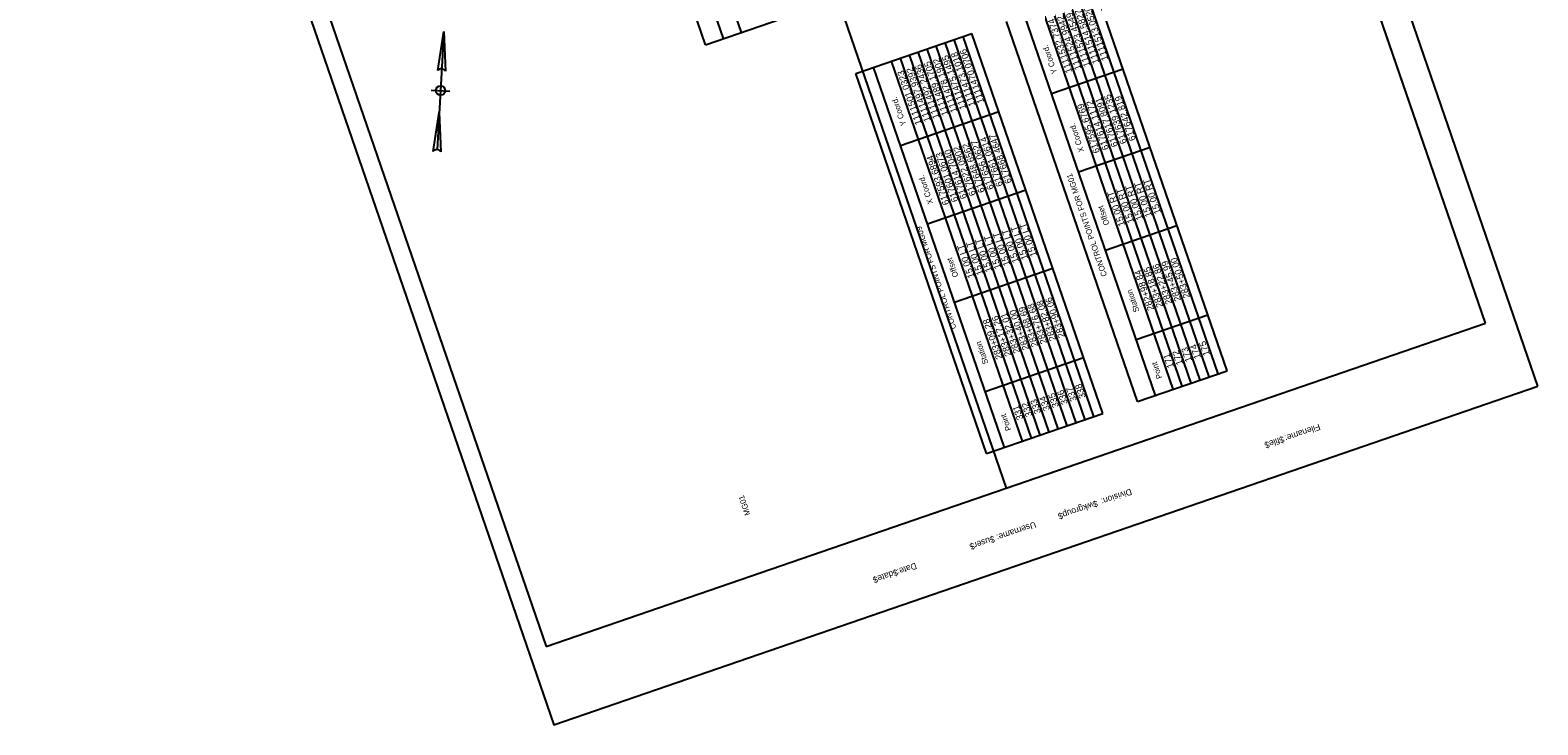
# Model space of a CAD drawing. Extents: x 1111039 to 1111836, y 617707 to 618808.
# Drawn here: x 1111039 to 1111836, y 617707 to 618074 of the extents above; entities that cross this region are included whole.
import ezdxf

# ---------------------------------------------------------------- set-up
doc = ezdxf.new("R2010")
doc.units = 0
for name, color, linetype in [('ANNOTATION', 7, 'Continuous'), ('BORDER', 7, 'Continuous'), ('CLIPS', 7, 'Continuous'), ('D_Roadway_Centerline_Text', 7, 'Continuous'), ('H_V CONTROLS', 7, 'Continuous'), ('PLOT BOUNDARY', 7, 'Continuous')]:
    doc.layers.add(name, color=color, linetype=linetype)

msp = doc.modelspace()

# ---------------------------------------------------------------- linework, layer by layer
at = {"layer": 'BORDER'}
for p, q in [((1111807.98, 617919.56), (1111547.52, 618675.97)), ((1111051.13, 618505.05), (1111311.58, 617748.63)), ((1111311.58, 617748.63), (1111807.98, 617919.56))]:
    msp.add_line(p, q, dxfattribs=at)
at = {"layer": 'CLIPS'}
msp.add_lwpolyline([(1111807.98, 617919.56), (1111563.8, 618628.7), (1111310.4, 618541.44), (1111554.58, 617832.3)], close=True, dxfattribs=at)
at = {"layer": 'H_V CONTROLS'}
for p, q in [((1111395.79, 618066.68), (1111326.61, 618267.61)), ((1111405.25, 618069.94), (1111336.06, 618270.86)), ((1111414.7, 618073.2), (1111345.52, 618274.12)), ((1111395.79, 618066.68), (1111584.9, 618131.8)), ((1111661.89, 617891.1), (1111592.71, 618092.02)), ((1111666.62, 617892.73), (1111597.44, 618093.65)), ((1111671.35, 617894.36), (1111602.17, 618095.28)), ((1111671.35, 617894.36), (1111602.17, 618095.28)), ((1111642.98, 617884.59), (1111573.8, 618085.51)), ((1111647.71, 617886.22), (1111578.53, 618087.14)), ((1111652.44, 617887.85), (1111583.26, 618088.77)), ((1111657.17, 617889.47), (1111587.98, 618090.4)), ((1111624.07, 617878.08), (1111554.89, 618079)), ((1111633.53, 617881.33), (1111564.35, 618082.26)), ((1111257.53, 618073.67), (1111253.89, 618011.28)), ((1111254.24, 618053), (1111257.53, 618073.67)), ((1111257.53, 618073.67), (1111258.4, 618052.75)), ((1111475.12, 618051.53), (1111536.57, 618072.69)), ((1111591.57, 617866.89), (1111522.39, 618067.81)), ((1111596.3, 617868.52), (1111527.12, 618069.44)), ((1111601.03, 617870.14), (1111531.85, 618071.07)), ((1111605.76, 617871.77), (1111536.57, 618072.69)), ((1111605.76, 617871.77), (1111536.57, 618072.69)), ((1111572.66, 617860.38), (1111503.48, 618061.3)), ((1111577.39, 617862), (1111508.21, 618062.93)), ((1111582.12, 617863.63), (1111512.94, 618064.55)), ((1111586.85, 617865.26), (1111517.66, 618066.18)), ((1111553.75, 617853.87), (1111484.57, 618054.79)), ((1111563.21, 617857.12), (1111494.03, 618058.04)), ((1111567.94, 617858.75), (1111498.75, 618059.67)), ((1111578.59, 618040.89), (1111616.41, 618053.91)), ((1111544.3, 617850.61), (1111475.12, 618051.53)), ((1111250.72, 618042.77), (1111260.7, 618042.18)), ((1111251.75, 618010.28), (1111255.04, 618030.96)), ((1111255.04, 618030.96), (1111255.91, 618010.04)), ((1111498.81, 618013.42), (1111550.82, 618031.33)), ((1111592.83, 617999.52), (1111630.65, 618012.55)), ((1111513.06, 617972.05), (1111565.06, 617989.96)), ((1111607.08, 617958.16), (1111644.9, 617971.18)), ((1111527.3, 617930.69), (1111579.3, 617948.59)), ((1111623.35, 617910.88), (1111661.17, 617923.9)), ((1111543.58, 617883.41), (1111595.58, 617901.32)), ((1111624.07, 617878.08), (1111671.35, 617894.36)), ((1111544.3, 617850.61), (1111605.76, 617871.77))]:
    msp.add_line(p, q, dxfattribs=at)
msp.add_circle((1111255.71, 618042.48), 2.5, dxfattribs=at)
for centre in [(1111256.24, 618051.5), (1111253.75, 618008.78)]:
    msp.add_arc(centre, 2.5, 30.21826, 143.10365, dxfattribs=at)
at = {"layer": 'PLOT BOUNDARY'}
msp.add_lwpolyline([(1111835.61, 617886.27), (1111558.88, 618689.96), (1111038.85, 618510.9), (1111315.58, 617707.21)], close=True, dxfattribs=at)

# ---------------------------------------------------------------- texts
at = {"layer": 'ANNOTATION'}
for s, height, p in [('1111514.5827', 3.5156, (1111603.9, 618057.31)), ('1111513.0520', 3.5156, (1111608.64, 618058.94)), ('1111532.7374', 3.5156, (1111589.65, 618052.41)), ('1111524.9942', 3.5156, (1111594.44, 618054.06)), ('1111523.4549', 3.5156, (1111599.2, 618055.7)), ('1111475.1495', 3.5156, (1111533.62, 618033.11)), ('1111473.1018', 3.5156, (1111538.41, 618034.76)), ('1111470.0706', 3.5156, (1111543.08, 618036.37)), ('1111501.0323', 3.5156, (1111510.09, 618025.01)), ('1111497.9392', 3.5156, (1111514.8, 618026.63)), ('1111492.2436', 3.5156, (1111519.42, 618028.23)), ('1111489.1705', 3.5156, (1111524.16, 618029.86)), ('1111478.1902', 3.5156, (1111528.93, 618031.5)), ('617614.1172', 3.5156, (1111609.03, 618011.67)), ('617617.8091', 3.5156, (1111613.8, 618013.31)), ('617639.1235', 3.5156, (1111618.49, 618014.92)), ('617642.819', 3.516, (1111623.23, 618016.55)), ('617595.6769', 3.5156, (1111604.24, 618010.02)), ('617622.0902', 3.5156, (1111538.76, 617987.47)), ('617648.6562', 3.5156, (1111543.52, 617989.11)), ('617656.0627', 3.5156, (1111548.22, 617990.72)), ('617661.0614', 3.5156, (1111553.01, 617992.37)), ('617668.4647', 3.5156, (1111557.68, 617993.98)), ('617593.6894', 3.5156, (1111524.68, 617982.62)), ('617601.0673', 3.5156, (1111529.4, 617984.24)), ('617614.7040', 3.5156, (1111534.02, 617985.84)), ('15.00 RT', 3.516, (1111617.55, 617971.39)), ('15.00 RT', 3.516, (1111622.34, 617973.04)), ('15.00 RT', 3.516, (1111627.1, 617974.68)), ('15.00 RT', 3.516, (1111631.79, 617976.29)), ('15.00 RT', 3.516, (1111636.53, 617977.92)), ('15.00 LT', 3.516, (1111552.06, 617948.84)), ('15.00 LT', 3.516, (1111556.83, 617950.48)), ('15.00 LT', 3.516, (1111561.52, 617952.09)), ('15.00 LT', 3.516, (1111566.31, 617953.74)), ('15.00 LT', 3.516, (1111570.98, 617955.35)), ('15.00 LT', 3.516, (1111537.98, 617943.99)), ('15.00 LT', 3.516, (1111542.7, 617945.61)), ('15.00 LT', 3.516, (1111547.32, 617947.21)), ('283+18.85', 3.516, (1111637.67, 617928.51)), ('283+22.86', 3.516, (1111642.43, 617930.15)), ('283+45.99', 3.516, (1111647.12, 617931.77)), ('283+50.00', 3.516, (1111651.87, 617933.4)), ('282+98.84', 3.516, (1111632.88, 617926.86)), ('283+90.06', 3.516, (1111585.75, 617912.43)), ('283+32.01', 3.516, (1111562.1, 617904.29)), ('283+40.00', 3.516, (1111566.84, 617905.92)), ('283+68.69', 3.516, (1111571.6, 617907.56)), ('283+76.68', 3.516, (1111576.3, 617909.18)), ('283+82.08', 3.516, (1111581.09, 617910.83)), ('283+09.28', 3.516, (1111552.76, 617901.07)), ('283+17.26', 3.516, (1111557.48, 617902.7)), ('175', 3.516, (1111662.33, 617903)), ('171', 3.516, (1111643.35, 617896.46)), ('172', 3.516, (1111648.13, 617898.11)), ('173', 3.516, (1111652.9, 617899.75)), ('174', 3.516, (1111657.59, 617901.37)), ('337', 3.516, (1111592.11, 617878.82)), ('338', 3.516, (1111596.78, 617880.43)), ('332', 3.516, (1111568.5, 617870.69)), ('333', 3.516, (1111573.12, 617872.28)), ('334', 3.516, (1111577.86, 617873.91)), ('335', 3.516, (1111582.63, 617875.55)), ('336', 3.516, (1111587.32, 617877.17)), ('331', 3.516, (1111563.78, 617869.06))]:
    msp.add_text(s, height=height, rotation=109, dxfattribs=at).set_placement(p)
at = {"layer": 'BORDER'}
for s, p in [('Filename:', (1111719.98, 617866.44)), ('$file$', (1111700.95, 617859.88)), ('Division:', (1111620.38, 617832.14)), ('$wkgroup$', (1111602.4, 617825.95)), ('Username:', (1111569.79, 617814.72)), ('$user$', (1111547.93, 617807.2)), ('$date$', (1111496.81, 617789.59)), ('Date:', (1111506.68, 617792.99))]:
    msp.add_text(s, height=3.348, rotation=199, dxfattribs=at).set_placement(p)
at = {"layer": 'D_Roadway_Centerline_Text'}
msp.add_text('MG01', height=3, rotation=108.7899, dxfattribs=at).set_placement((1111419.49, 617818.5))
at = {"layer": 'H_V CONTROLS'}
for s, p in [('Y Coord.', (1111581.67, 618051.91)), ('Y Coord.', (1111501.9, 618024.44)), ('X Coord.', (1111595.91, 618010.54)), ('X Coord.', (1111516.14, 617983.07)), ('CONTROL POINTS FOR MG01', (1111607.99, 617944.76)), ('Offset', (1111609.24, 617971.84)), ('CONTROL POINTS FOR MG09', (1111528.35, 617916.89)), ('Offset', (1111529.46, 617944.37)), ('Station', (1111625.06, 617925.89)), ('Station', (1111545.28, 617898.43)), ('Point', (1111637.17, 617890.71)), ('Point', (1111557.4, 617863.25))]:
    msp.add_text(s, height=3, rotation=109, dxfattribs=at).set_placement(p)

doc.saveas('drawing.dxf')
